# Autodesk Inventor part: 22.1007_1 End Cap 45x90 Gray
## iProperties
Created: 2012-02
Part Number: 22.1007_1 End Cap 45x90 Gray
Document SubType Name: Modeling
Designer: Administrator
Density: 1.06 g/cm^3
Material: ABS Plastic
Mass: 10.9481 g
Surface Area: 108.264 cm^2
Volume: 10.3284 cm^3
Author: Administrator
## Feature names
1. Base1
